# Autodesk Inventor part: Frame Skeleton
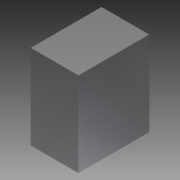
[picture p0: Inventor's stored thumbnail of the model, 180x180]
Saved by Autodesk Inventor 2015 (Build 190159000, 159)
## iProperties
Created: 2007-02
Part Number: Frame Skeleton
Document SubType Name: Modeling
Designer: Autodesk, Inc.
Density: 1 g/cm^3
Mass: 345395 g
Surface Area: 30419 cm^2
Volume: 345395 cm^3
Material: Generic
Appearance: Light Gray Reflective
Author: Autodesk, Inc.
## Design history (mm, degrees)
sketch "Sketch1"
  geometry: L1 (0, 850)-(-508, 850); L2 (-508, 850)-(-508, -50.8); L3 (-508, -50.8)-(0, -50.8); L4 (0, -50.8)-(0, 850); 2 further points
  constraints: 8 end point, 2 parallel, 1 horizontal, 1 perpendicular, 2 other
  dimensions: "d2" = 900.8 distance of L3.end L1.start
extrude "Extrusion1" new body sketch "Sketch1" distance "d0" = 754.7864; taper "d1" = 0 deg
body "Solid1"
